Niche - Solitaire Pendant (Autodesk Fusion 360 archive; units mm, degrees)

design "Solitaire" references "G30 - Globe Bulb", "Ketra - A20 Tunable Lamp", "Luxe Single Pendant Cordset - 4ft Standard", "Solitaire"
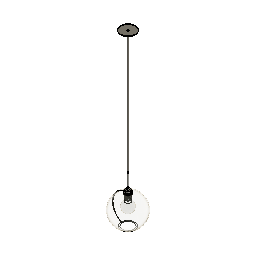
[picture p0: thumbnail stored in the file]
external_derived "ExternalDerived"
external_derived "ExternalDerived" bodies "Canopy"
move "Move1" TranslateX 0 TranslateY 0 TranslateZ 50.038
move "Move2"
offset_faces "OffsetFaces1" distance -12.7
external_derived "ExternalDerived3" bodies "Ketra A-20"
move "Move3"
external_derived "ExternalDerived4" bodies "G30 - Bulb", "G30 - E26"
move "Move4"
move "Move5"
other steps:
derived_base_feature "Derived Base Feature" bodies "Body1", "Solitaire"
derived_base_feature "Derived Base Feature2" bodies "Socket Body", "Shade Ring", "Shade Ring +Collar", "Socket", "Body1 (1)", "Metal Strain Relief", "Fabric Cord (1)", "Stem (Threaded)"
derived_base_feature "Derived Base Feature3" bodies "Ketra A-20"
derived_base_feature "Derived Base Feature4" bodies "G30 - Bulb", "G30 - E26"
named bodies: "Body1", "Solitaire", "Socket Body", "Shade Ring", "Shade Ring +Collar", "Socket", "Body1 (1)", "Metal Strain Relief", "Fabric Cord (1)", "Stem (Threaded)", "Cap (Threaded)", "Canopy", "Ketra A-20", "G30 - Bulb", "G30 - E26"

design "Luxe Canopy - Single Pendant Cordset" references "Canopy Mounting Bar Screw", "Plastic Strain Relief", "M5 Set Screw", "Canopy Mounting Bar", "Luxe Cordset"
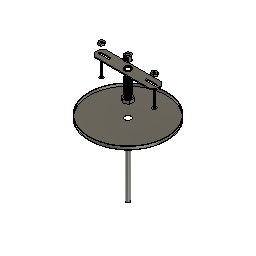
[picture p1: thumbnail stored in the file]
sketch "Sketch1" plane through (0, 0, 0) normal (0, 0, 1) x axis (1, 0, 0)
  circle C1 centre (0, 0) radius 63.5
  point P1 (0, 0)
  point P2 (0, 0)
  coincident P1 P2
  dimension "d1" diameter C1 = 127
extrude "Extrude1" new body sketch "Sketch1" along normal blind 5.08
shell "Shell1" innerThickness 0.762
hole "Hole1" HoleDepth 35.56 HoleDiameter 10.16 TipAngle 118
component_from_bodies "Body->Comp1"
component_insert "Component Insert1"
component_insert "Component Insert2"
component_insert "Component Insert3"
sketch "Sketch2" plane through (0, 0, 0) normal (0, 0, 1) x axis (1, 0, 0)
  circle C1 centre (0, 0) radius 3.175
  point P1 (0, 0)
  point P2 (0, 0)
  coincident P1 P2
  dimension "d8" diameter C1 = 6.35
extrude "Extrude2" new body sketch "Sketch2" along normal blind 127 and against normal blind 127 bodies "Fabric Cord"
component_insert "Component Insert4"
component_insert "Component Insert5"
position "Position1"
sketch "Sketch3" plane through (0, 0, 0.762) normal (0, 0, 1) x axis (-1, 0, 0)
  circle C1 centre (-0.0475, 0.2257) radius 5.08
  circle C2 centre (0, 0) radius 62.738
  circle C3 centre (0, 0) radius 4.826
  concentric C2 C3
  dimension "d13" diameter C3 = 9.652
extrude "Extrude3" new body sketch "Sketch3" profile of C3 along normal blind 25.4 bodies "Threaded Nipple"
shell "Shell2" innerThickness 1.27
thread "Thread1"
sketch "Sketch5" plane through (0, 0, 127) normal (0, 0, 1) x axis (-1, 0, 0)
  line L1 (-6.8191, 3.937) -> (0, 7.874)
  line L2 (-6.8191, -3.937) -> (-6.8191, 3.937)
  line L3 (0, -7.874) -> (-6.8191, -3.937)
  line L4 (6.8191, -3.937) -> (0, -7.874)
  line L5 (6.8191, 3.937) -> (6.8191, -3.937)
  line L6 (0, 7.874) -> (6.8191, 3.937)
  circle C1 centre (0, 0) radius 3.175
  point P2 (0, 0)
  point P9 (0, 0)
  point P3 (0, 7.874)
  coincident P2 P9
  dimension "d20" distance P3 P9 = 7.874
extrude "Extrude4" new body sketch "Sketch5" along normal blind 5.08 bodies "Hex Nut"
move "Move1"
thread "Thread2"
move "Move2" TranslateX 0 TranslateY 0 TranslateZ -55.88
move "Move3" TranslateX 0 TranslateY 0 TranslateZ 60.96
position "Position2"
sketch "Sketch6" plane through (0, 0, 0) normal (0, 0, 1) x axis (1, 0, 0)
  circle C1 centre (0, 0) radius 9.525
  point P1 (0, 0)
  point P2 (0, 0)
  coincident P1 P2
  dimension "d29" diameter C1 = 19.05
extrude "Extrude5" new body sketch "Sketch6" along normal blind 16.129 bodies "Metal Strain Relief"
move "Move4" TranslateX 0 TranslateY 0 TranslateZ -86.36
hole "Hole2" HoleDepth 10.16 HoleDiameter 5.08 TipAngle 118
hole "Hole3" HoleDepth 4.064 HoleDiameter 7.62 TipAngle 180
hole "Hole4" HoleDepth 12.192 HoleDiameter 9.144 TipAngle 180
thread "Thread3" ThreadOffset 0 ThreadLength 6.096
move "Move1" TranslateX 0 TranslateY 0 TranslateZ 68.58
move "Move5" TranslateX 0 TranslateY 0 TranslateZ 138.43
component_insert "Component Insert6"
external_derived "ExternalDerived1" bodies "5M Set Screw"
move "Move6" TranslateX 0 TranslateY 0 TranslateZ -185.42
copy_paste_bodies "CopyPasteBodies1"
move "Move7" TranslateX 0 TranslateY 0 TranslateZ -12.7
offset_faces "OffsetFaces1" distance -152.4
move "Move8"
component_from_bodies "Body->Comp2"
component_from_bodies "Body->Comp3"
component_from_bodies "Body->Comp4"
component_from_bodies "Body->Comp5"
hole "Hole1" HoleDepth 25.4 HoleDiameter 6.35 TipAngle 180
sketch "Sketch7" plane through (0, 0, 0) normal (0, 0, 1) x axis (1, 0, 0)
  line L1 (49.784, 3.9595) -> (52.07, 0)
  line L2 (45.212, 3.9595) -> (49.784, 3.9595)
  line L3 (42.926, 0) -> (45.212, 3.9595)
  line L4 (45.212, -3.9595) -> (42.926, 0)
  line L5 (49.784, -3.9595) -> (45.212, -3.9595)
  line L6 (52.07, 0) -> (49.784, -3.9595)
  point P2 (52.07, 0)
  point P8 (47.498, 0)
  dimension "d63" distance P2 P8 = 4.572
extrude "Extrude6" new body sketch "Sketch7" along normal blind 3.175 bodies "Mounting Hex Nut"
hole "Hole5" HoleDepth 25.4 HoleDiameter 3.81 TipAngle 180
thread "Thread4"
move "Move9"
component_from_bodies "Body->Comp6"
copy_paste "CopyPaste1"
move "Move10"
derived_base_feature "Derived Base Feature3" bodies "Stem (Threaded)", "Cap 9Threaded)"
move "Move11"
component_from_bodies "Body->Comp7"
component_from_bodies "Body->Comp8"
component_from_bodies "Body->Comp9"
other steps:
base_feature "Base Feature1"
base_feature "Base Feature1" bodies "Stem (Threaded)"
base_feature "Base Feature1" bodies "Cap 9Threaded)"
base_feature "Base Feature1" bodies "Fabric Cord"
base_feature "Base Feature1" bodies "Metal Strain Relief"
base_feature "Base Feature1" bodies "Mounting Hex Nut"
base_feature "Base Feature1" bodies "Hex Nut"
base_feature "Base Feature1" bodies "Fabric Cord (1)"
base_feature "Base Feature1" bodies "Threaded Nipple"
derived_base_feature "Derived Base Feature1" bodies "Socket Body", "Shade Ring", "Shade Ring +Collar", "Socket", "Rigid Stem"
derived_base_feature "Derived Base Feature2" bodies "5M Set Screw"
base_feature "Base Feature1" bodies "Fabric Cord", "Fabric Cord (1)"
create_component "CreateComponent1"
remove_body "RemoveBody1"
create_component "CreateComponent2"
remove_body "RemoveBody2"
create_component "CreateComponent3"
remove_body "RemoveBody3"
create_component "CreateComponent4"
remove_body "RemoveBody4"
create_component "CreateComponent5"
remove_body "RemoveBody5"
create_component "CreateComponent6"
remove_body "RemoveBody6"
create_component "CreateComponent7"
remove_body "RemoveBody7"
create_component "CreateComponent8"
remove_body "RemoveBody8"
create_component "CreateComponent9"
remove_body "RemoveBody9"
named bodies: "Fabric Cord", "Threaded Nipple", "Hex Nut", "Metal Strain Relief", "Socket Body", "Shade Ring", "Shade Ring +Collar", "Socket", "Rigid Stem", "5M Set Screw", "Fabric Cord (1)", "Mounting Hex Nut", "Stem (Threaded)", "Cap 9Threaded)"

design "Solitaire" references "Niche_Solitaire_Single_Pendant_NURBS"
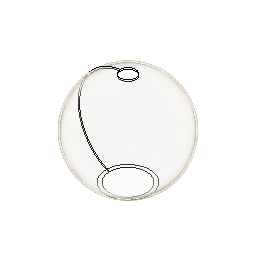
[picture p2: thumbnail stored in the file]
external_derived "ExternalDerived" bodies "Solitaire"
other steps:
derived_base_feature "Derived Base Feature" bodies "Solitaire"
named bodies: "Solitaire"

design "M5 Set Screw"
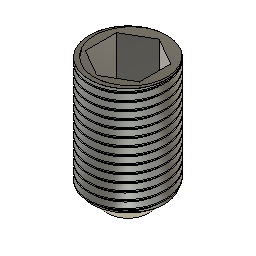
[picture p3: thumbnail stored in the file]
sketch "Sketch1" plane through (0, 0, 0) normal (0, 0, 1) x axis (1, 0, 0)
  circle C1 centre (0, 0) radius 2.5
  point P1 (0, 0)
  point P2 (0, 0)
  coincident P1 P2
  dimension "d1" diameter C1 = 5
extrude "Extrude1" new body sketch "Sketch1" along normal blind 8
sketch "Sketch2" plane through (0, 0, 8) normal (0, 0, 1) x axis (-1, 0, 0)
  line L1 (-1.7321, 1) -> (0, 2)
  line L2 (-1.7321, -1) -> (-1.7321, 1)
  line L3 (0, -2) -> (-1.7321, -1)
  line L4 (1.7321, -1) -> (0, -2)
  line L5 (1.7321, 1) -> (1.7321, -1)
  line L6 (0, 2) -> (1.7321, 1)
  circle C1 centre (0, 0) radius 2.5
  point P2 (0, 0)
  point P9 (0, 0)
  coincident P2 P9
extrude "Extrude2" cut sketch "Sketch2" profile of L1 L2 L3 L4 L5 L6 against normal blind 3
thread "Thread1" ThreadOffset 0.99 ThreadLength 7
chamfer "Chamfer1" distance 1.15

design "Luxe Cordset" references "M5 Set Screw"
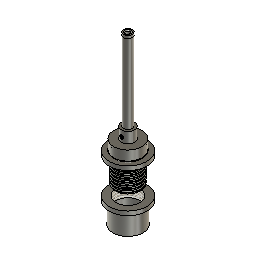
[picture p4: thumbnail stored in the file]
sketch "Sketch1" plane through (0, 0, 0) normal (0, 0, 1) x axis (1, 0, 0)
  circle C1 centre (0, 0) radius 20.6
  point P1 (0, 0)
  point P2 (0, 0)
  coincident P1 P2
  dimension "d11" diameter C1 = 41.2
extrude "Extrude1" new body sketch "Sketch1" along normal blind 14 bodies "Socket Body"
sketch "Sketch2" plane through (0, 0, 14) normal (0, 0, 1) x axis (-1, 0, 0)
  circle C1 centre (0, 0) radius 20.6
  circle C2 centre (0, 0) radius 9.6
  concentric C1 C2
  dimension "d3" diameter C2 = 19.2
extrude "Extrude2" add sketch "Sketch2" profile of C2 along normal blind 15.75
sketch "Sketch3" plane through (0, 0, 29.75) normal (0, 0, 1) x axis (-1, 0, 0)
  circle C1 centre (0, 0) radius 9.6
  circle C2 centre (0, 0) radius 5.75
  concentric C1 C2
  dimension "d6" diameter C2 = 11.5
extrude "Extrude3" new body sketch "Sketch3" profile of C2 along normal blind 114 bodies "Rigid Stem"
move "Move1"
sketch "Sketch4" plane through (0, 0, 203.75) normal (0, 0, 1) x axis (-1, 0, 0)
  circle C1 centre (0, 0) radius 5.75
  circle C2 centre (0, 0) radius 27.5
  dimension "d10" diameter C2 = 55
extrude "Extrude4" new body sketch "Sketch4" profile of C2 along normal blind 6 bodies "Shade Ring"
hole "Hole1" HoleDepth 25 HoleDiameter 42.75 TipAngle 118
sketch "Sketch5" plane through (0, 0, 0) normal (0, 0, 1) x axis (1, 0, 0)
  circle C1 centre (0, 0) radius 22
  point P1 (0, 0)
  point P2 (0, 0)
  coincident P1 P2
  dimension "d18" diameter C1 = 44
move "Move2"
copy_paste_bodies "CopyPasteBodies1"
move "Move3"
sketch "Sketch6" plane through (0, 0, 60) normal (0, 0, -1) x axis (1, 0, 0)
  circle C1 centre (0, 0) radius 20.6
  circle C2 centre (0, 0) radius 21.375
  circle C3 centre (0, 0) radius 20
  concentric C1 C2
  concentric C1 C3
  dimension "d21" diameter C2 = 42.75
  dimension "d24" diameter C3 = 40
cylinder_primitive "CylinderPrimitive1" Height 8 Diameter 42.75
thread "Thread1"
thread "Thread3"
hole "Hole2" HoleDepth 18 HoleDiameter 39 TipAngle 180
move "Move4"
move "Move5"
move "Move6"
hole "Hole3" HoleDepth 114 HoleDiameter 7.6 TipAngle 180
derived_base_feature "Derived Base Feature" bodies "Socket"
move "Move7"
scale "Scale1" ScaleX 1.2 ScaleY 1.2
move "Move8"
sketch "Sketch8" plane through (0, 0, -23.9827) normal (0, 0, -1) x axis (1, 0, 0)
  circle C1 centre (0, -0.036) radius 27.5
  circle C2 centre (0, -0.036) radius 22
  circle C3 centre (0, -0.036) radius 19.5
  dimension "d36" diameter C2 = 44
  dimension "d42" = -2.5
extrude "Extrude7" add sketch "Sketch8" profile of C2 C3 along normal blind 30
offset_faces "OffsetFaces1" distance 2.75
offset_faces "OffsetFaces2" distance -9
thread "Thread2"
move "Move9"
move "Move10"
move "Move11"
scale "Scale2" ScaleZ 1.2
move "Move12"
move "Move13"
move "Move14"
move "Move15"
move "Move16"
split_face "SplitFace1"
move "Move17"
move "Move18"
move "Move19"
move "Move20"
move "Move21"
move "Move22"
move "Move23"
move "Move24"
move "Move25"
move "Move26"
move "Move27"
thread "Thread4"
move "Move28"
move "Move29"
move "Move30"
hole "Hole4" HoleDepth 21 HoleDiameter 39.35 TipAngle 180
hole "Hole5" HoleDepth 9 HoleDiameter 5 TipAngle 180
move "Move31"
move "Move32"
hole "Hole6" HoleDepth 20 HoleDiameter 10 TipAngle 180
move_face "MoveFace3"
move "Move33"
move "Move34"
move "Move35"
move "Move36"
move "Move37"
thread "Thread5" ThreadOffset 0 ThreadLength 6
thread "Thread6" ThreadOffset 0 ThreadLength 6
move "Move38"
move "Move39"
move "Move40"
move "Move41"
component_insert "Component Insert"
thread "Thread7" ThreadOffset 0.5 ThreadLength 5.337
chamfer "Chamfer1" distance 0.5 distance 0.35
sketch "Sketch12" plane through (0, 0, 0) normal (0, 0, 1) x axis (1, 0, 0)
  circle C1 centre (0, 0) radius 6.35
  dimension "d60" diameter C1 = 12.7
extrude "Extrude8" new body sketch "Sketch12" along normal blind 115 bodies "Stem (Threaded)"
hole "Hole7" HoleDepth 115 HoleDiameter 9.65 TipAngle 118
thread "Thread8" ThreadOffset 0 ThreadLength 12.5
thread "Thread9" ThreadOffset 0 ThreadLength 12.5
sketch "Sketch13" plane through (0, 0, 0) normal (0, 0, 1) x axis (1, 0, 0)
  circle C1 centre (0, 0) radius 6.35
  point P1 (0, 0)
  point P2 (0, 0)
  coincident P1 P2
  dimension "d70" diameter C1 = 12.7
extrude "Extrude9" new body sketch "Sketch13" along normal blind 4 bodies "Cap 9Threaded)"
sketch "Sketch14" plane through (0, 0, 4) normal (0, 0, 1) x axis (-1, 0, 0)
  circle C1 centre (0, 0) radius 6.35
  circle C2 centre (0, 0) radius 4.5
  concentric C1 C2
  dimension "d73" diameter C2 = 9
extrude "Extrude10" add sketch "Sketch14" profile of C2 against normal blind 14
thread "Thread10"
hole "Hole8" HoleDepth 115 HoleDiameter 6.5 TipAngle 118 CSDiameter 9 CSAngle 90
move "Move42"
move "Move43"
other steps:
base_feature "Base Feature" bodies "Shade Ring +Collar"
named bodies: "Socket Body", "Shade Ring", "Shade Ring +Collar", "Socket", "Rigid Stem", "Stem (Threaded)", "Cap 9Threaded)"

design "G30 - Globe Bulb"
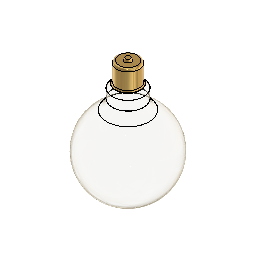
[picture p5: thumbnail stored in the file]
sketch "Sketch1" plane through (0, 0, 0) normal (0, 1, 0) x axis (1, 0, 0)
  line L1 (0, -66.04) -> (0, 46.99)
  line L2 (17.78, -51.3212) -> (17.78, -61.849)
  line L3 (-17.78, -61.849) -> (-17.78, -51.3212)
  line L4 (-17.78, -61.849) -> (-13.589, -66.04)
  line L5 (17.78, -61.849) -> (13.589, -66.04)
  line L6 (-17.526, -61.7438) -> (-17.526, -51.3212)
  line L7 (-17.526, -61.7438) -> (-13.4838, -65.786)
  line L8 (17.526, -61.7438) -> (13.4838, -65.786)
  line L9 (17.526, -51.3212) -> (17.526, -61.7438)
  line L10 (-12.7, -66.04) -> (-13.589, -66.04)
  line L11 (13.589, -66.04) -> (12.7, -66.04)
  line L12 (-12.7, -65.786) -> (-13.4838, -65.786)
  line L13 (13.4838, -65.786) -> (12.7, -65.786)
  line L14 (-12.7, -66.04) -> (-12.7, -65.786)
  line L15 (12.7, -66.04) -> (12.7, -65.786)
  arc A1 centre (0, 0) radius 46.99 clockwise from (-23.9949, -40.4018) to (23.9949, -40.4018)
  arc A2 centre (-30.48, -51.3212) radius 12.7 clockwise from (-23.9949, -40.4018) to (-17.78, -51.3212)
  arc A3 centre (30.48, -51.3212) radius 12.7 clockwise from (17.78, -51.3212) to (23.9949, -40.4018)
  arc A4 centre (30.48, -51.3212) radius 12.954 clockwise from (17.526, -51.3212) to (23.8652, -40.1834)
  arc A5 centre (0, 0) radius 46.736 clockwise from (-23.8652, -40.1834) to (23.8652, -40.1834)
  arc A6 centre (-30.48, -51.3212) radius 12.954 clockwise from (-23.8652, -40.1834) to (-17.526, -51.3212)
  point P1 (0, 0)
  point P2 (0, 0)
  point P3 (0, 46.99)
  point P5 (17.78, -66.04)
  point P8 (13.589, -66.04)
  point P9 (17.78, -61.849)
  coincident P1 P2
  coincident P3 A1
  vertical L1
  horizontal L10
  vertical L2
  vertical L3
  coincident P5 L10
  coincident P5 L2
  tangent L3 A2
  tangent A1 A2
  tangent L2 A3
  tangent A1 A3
  collinear L10 L11
  parallel L3 L6
  parallel L4 L7
  parallel L5 L8
  parallel L2 L9
  concentric A3 A4
  concentric A1 A5
  concentric A2 A6
  tangent L6 A6
  tangent A5 A6
  tangent A4 A5
  tangent L9 A4
  collinear L12 L13
  dimension "d5" distance P5 P8 = 4.191
  dimension "d6" distance P5 P9 = 4.191 (= "d5")
  dimension "d7" radius A2 = 12.7
  dimension "d8" radius A3 = 12.7
sketch "Sketch2" plane through (0, 0, 0) normal (0, 1, 0) x axis (1, 0, 0)
  line L1 (13.97, -66.04) -> (-13.97, -66.04)
  line L2 (13.97, -66.548) -> (13.97, -66.04)
  line L3 (-13.97, -66.04) -> (-13.97, -66.548)
  line L4 (-2.54, -91.44) -> (2.5497, -91.44)
  line L5 (-3.81, -88.9) -> (-2.54, -91.44)
  line L6 (3.81, -88.9) -> (2.5497, -91.44)
  line L7 (-10.16, -88.9) -> (-3.81, -88.9)
  line L8 (-12.7, -68.58) -> (-12.7, -86.36)
  line L9 (-12.7, -67.818) -> (-12.7, -68.58)
  line L10 (-13.97, -66.548) -> (-13.97, -66.548)
  line L11 (10.16, -88.9) -> (3.81, -88.9)
  line L12 (12.7, -67.818) -> (12.7, -86.36)
  line L13 (13.97, -66.548) -> (13.97, -66.548)
  line L14 (-2.54, -91.44) -> (2.5497, -91.44)
  line L15 (0, 46.99) -> (0.0049, -91.44)
  arc A1 centre (-10.16, -86.36) radius 2.54 clockwise from (-10.16, -88.9) to (-12.7, -86.36)
  arc A2 centre (10.16, -86.36) radius 2.54 clockwise from (12.7, -86.36) to (10.16, -88.9)
  arc A3 centre (-13.97, -67.818) radius 1.27 clockwise from (-13.97, -66.548) to (-12.7, -67.818)
  arc A4 centre (13.97, -67.818) radius 1.27 clockwise from (12.7, -67.818) to (13.97, -66.548)
  point P23 (0, 46.99)
  point P25 (0, 46.99)
  horizontal L1
  vertical L2
  vertical L3
  horizontal L4
  perpendicular L7 L8
  perpendicular L7 L9
  perpendicular L4 L12
  tangent L7 A1
  tangent L8 A1
  tangent L11 A2
  tangent L12 A2
  equal A1 A2
  tangent L9 A3
  tangent L12 A4
  coincident P23 P25
  dimension "d12" radius A1 = 2.54
  dimension "d13" radius A3 = 1.27
  dimension "d14" radius A4 = 1.27
revolve "Revolve1" sketch "Sketch1" AlongAngle 360
revolve "Revolve2" sketch "Sketch2" AlongAngle 360

design "Niche_Solitaire_Single_Pendant_NURBS"
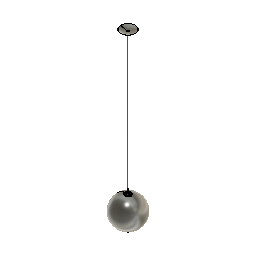
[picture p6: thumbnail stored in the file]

design "Plastic Strain Relief"
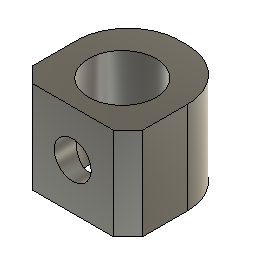
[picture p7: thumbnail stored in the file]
base_feature "Base Feature" bodies "strainrelief"
named bodies: "strainrelief"

design "Canopy Mounting Bar Screw"
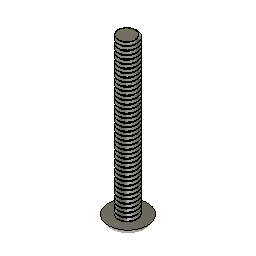
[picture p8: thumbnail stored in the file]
base_feature "Base Feature" bodies "screw1"
named bodies: "screw1"

design "Ketra - A20 Tunable Lamp"
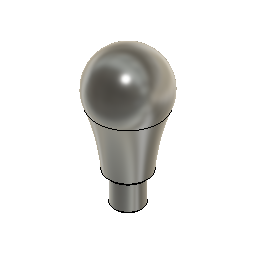
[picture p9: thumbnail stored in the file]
sketch "Sketch1" plane through (0, 0, 0) normal (0, 1, 0) x axis (1, 0, 0)
  line L1 (0, -125.73) -> (0, 0)
  line L2 (-10.795, -2.54) -> (-5.08, -2.54)
  line L3 (-12.7, -27.94) -> (-12.7, -4.445)
  line L4 (-15.2283, -27.9434) -> (-17.7637, -30.4805)
  line L5 (-2.54, 0) -> (-5.08, -2.54)
  curve K1 (-29.0564, -81.176) -> (-17.7637, -30.4805)
  curve K2 (-31.427, -87.6527) -> (-26.6858, -74.6994)
  line L6 (-15.2283, -27.9434) -> (-12.7, -27.94)
  line L7 (-2.54, 0) -> (0, 0)
  line L8 (-12.7, -4.445) -> (-10.795, -2.54)
  arc A1 centre (0, -93.974) radius 31.75 clockwise from (0, -125.724) to (-29.0564, -81.176)
  point P1 (0, 0)
  point P3 (0, 0)
  point P2 (0, -93.974)
  point P10 (0, -125.724)
  point P9 (-29.0564, -81.176)
  point P15 (0, 0)
  point P5 (-12.7, -2.54)
  point P16 (-10.795, -2.54)
  point P17 (-12.7, -4.445)
  coincident P1 P3
  vertical L1
  coincident P2 L1
  horizontal L2
  vertical L3
  coincident L1 P10
  midpoint P9 K2
  coincident P1 P15
  perpendicular L1 L7
  coincident P5 L2
  coincident P5 L3
  dimension "d1" distance P5 P16 = 1.905
  dimension "d2" distance P5 P17 = 1.905 (= "d1")
revolve "Revolve1" sketch "Sketch1" AlongAngle 360

design "Canopy Mounting Bar"
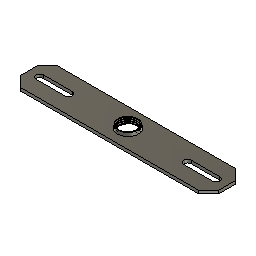
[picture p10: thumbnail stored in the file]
base_feature "Base Feature" bodies "mountingbar"
named bodies: "mountingbar"

design "Luxe Single Pendant Cordset - 4ft Standard" references "Luxe Canopy - Single Pendant Cordset"
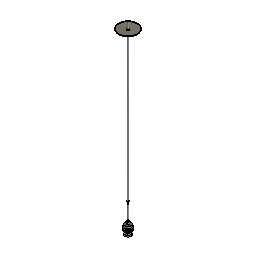
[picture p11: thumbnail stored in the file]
external_derived "ExternalDerived2" bodies "Cap (Threaded)"
move "Move1"
move "Move2"
offset_faces "OffsetFaces1" distance 1092.2
move "Move3"
move "Move4"
move "Move5"
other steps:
derived_base_feature "Derived Base Feature9" bodies "Socket Body", "Shade Ring", "Shade Ring +Collar", "Socket"
derived_base_feature "Derived Base Feature10" bodies "Body1"
derived_base_feature "Derived Base Feature12" bodies "Metal Strain Relief"
derived_base_feature "Derived Base Feature13" bodies "Fabric Cord (1)"
derived_base_feature "Derived Base Feature14" bodies "Stem (Threaded)"
derived_base_feature "Derived Base Feature15" bodies "Cap 9Threaded)", "Cap (Threaded)"
named bodies: "Socket Body", "Shade Ring", "Shade Ring +Collar", "Socket", "Metal Strain Relief", "Fabric Cord (1)", "Stem (Threaded)", "Cap 9Threaded)", "Body1", "Cap (Threaded)", "5M Set Screw"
